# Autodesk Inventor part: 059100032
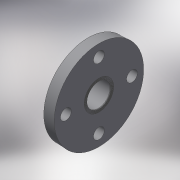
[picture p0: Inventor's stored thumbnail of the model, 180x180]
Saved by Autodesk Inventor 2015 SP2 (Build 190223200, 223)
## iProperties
Created: 2017-10
Part Number: 059100032
Material: Generic
Description: PLASSON FIXED FLANGE-CEM PVC 32
Document SubType Name: Modeling
Designer: KIM
Density: 1 g/cm^3
Appearance: Default
Author: KIM
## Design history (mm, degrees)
derived "059200.ipt"
feature "Solid1::059200.ipt"
tag "TaggingFeature1"
body "Solid1"
other parameters: "d0" = 23, "d2" = 115, "d3" = 113.85, "d14" = 14, "d15" = 42.5, "d16" = 23, "d17" = 0, "d19" = 360 deg, "d21" = 22, "d22" = 32, "d23" = 30.4, "d24" = 38.4, "d25" = 0.32, "d26" = 0.575, "d27" = 0.575, "d28" = 0.575, "d29" = 0.575, "d30" = 0.575, "d31" = 0.575, "d32" = 0.23, "d33" = 0, "d34" = 14, "E_" = 115, "H_" = 23, "Dp_" = 85, "S_" = 14, "l_" = 22, "d_" = 32, "H_1" = 14
